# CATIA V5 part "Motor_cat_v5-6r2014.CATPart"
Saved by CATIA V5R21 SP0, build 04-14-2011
Part number: Motor
Bounding box of the stored display mesh (mm): x -152.4 to 152.4, y -76.2 to 165.1, z -171.45 to 152.4
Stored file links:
  D:\CATIA V5R21 E-RESOURCES\CATIA-V5R21\catia-v5r21-Tut\c12-catia-v5r21-tut\c12-catia-v5r21-tut01\Motor_cat_v5r21.CATPart
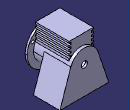
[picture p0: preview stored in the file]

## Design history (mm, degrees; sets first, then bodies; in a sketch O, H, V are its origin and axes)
Body1 (main body)
  Sketch1 on zx-plane, origin (0, 0, 0), H (-1, 0, 0), V (0, 0, 1)
    arc A1 centre (0, 0) radius 88.9 from (84.1413, 28.6959) to (-84.1413, 28.6959) ccw
    line L1 (-152.4, -171.45) -> (152.4, -171.45)
    point P1 (-152.4, -171.45)
    line L2 (152.4, -171.45) -> (84.1413, 28.6959)
    line L3 (-152.4, -171.45) -> (-84.1413, 28.6959)
    point P4 (-84.1413, 28.6959)
    point P5 (-84.1413, 28.6959)
    radius A1 = 88.9
    length L1 = 304.8
    distance V P1 = 152.4
    distance H L1 = 171.45
    horizontal: L1 H
    tangency: L3 A1, L2 A1
    coincidence: L3 P5, P4 A1, P4 P5
  Pad1: profile Sketch1, direction (0, 1, 0), length 165.1
  Sketch2 on face of Pad1, origin (0, 165.1, 0), H (-1, 0, 0), V (0, 0, 1)
    circle A1 centre (0, 0) radius 88.9
    reference projected arc E1 centre (0, 0) radius 88.9 from (84.1413, 28.6959) to (-84.1413, 28.6959) ccw from edge of Pad1
    tangency: A1 E1
  Pad2: profile Sketch2, direction (0, -1, 0), length 228.6
  Sketch3 on xy-plane, origin (0, 0, 0), H (1, 0, 0), V (0, 1, 0)
    line L1 (-76.2, 146.05) -> (76.2, 146.05)
    line L2 (76.2, 146.05) -> (76.2, -63.5)
    line L3 (76.2, -63.5) -> (-76.2, -63.5)
    line L4 (-76.2, -63.5) -> (-76.2, 146.05)
    reference projected line E1 (-88.9, -63.5) -> (88.9, -63.5) from edge of Pad2
    reference projected line E2 (84.1413, 165.1) -> (-84.1413, 165.1) from edge of Pad1
    length L1 = 152.4
    distance L4 V = 76.2
    distance E2 L1 = 19.05
    horizontal: L1 H, L3 H
    vertical: L2 V, L4 V
    coincidence: E1 L3
  Pad3: profile Sketch3, direction (0, 0, 1), length 152.4
  Sketch4 on face of Pad2, origin (0, -63.5, 0), H (1, 0, 0), V (0, 0, 1)
    circle A1 centre (0, 0) radius 127
    radius A1 = 127
  Pad4: profile Sketch4, direction (0, -1, 0), length 12.7
  Sketch5 on face of Pad3, origin (0, 146.05, 0), H (-1, 0, 0), V (0, 0, 1)
    line L1 (-76.2, 73.152) -> (-63.5, 73.152)
    line L2 (-63.5, 73.152) -> (-63.5, 61.722)
    line L3 (-63.5, 61.722) -> (-76.2, 61.722)
    line L4 (-76.2, 61.722) -> (-76.2, 73.152)
    reference projected line E1 (-76.2, 0) -> (-76.2, 152.4) from edge of Pad3
    length L1 = 12.7
    length L2 = 11.43
    distance L3 H = 61.722
    horizontal: L1 H, L3 H
    vertical: L2 V, L4 V
    coincidence: L4 E1
  Pocket1: profile Sketch5, direction (0, -1, 0), length 209.55
  RectPattern1: of Pocket1, direction 1 instances 4, spacing 22.86, along edge of Pad3 reversed, direction 2 instances 2, spacing 139.7, along edge of Pad3
  Sketch6 on face of Pad4, origin (0, -76.2, 0), H (1, 0, 0), V (0, 0, 1)
    circle A1 centre (0, -107.95) radius 9.525
    point P1 (0, -107.95)
    radius A1 = 9.525
    distance P1 H = 107.95
    coincidence: P1 V
  Pocket2: profile Sketch6, direction (0, 1, 0), length 12.7
  CircPattern1: of Pocket2, instances 3, angular step 120, axis from face
  Sketch7 on face of Pad4, origin (0, -76.2, 0), H (1, 0, 0), V (0, 0, 1)
    circle A1 centre (0, 0) radius 76.2
    circle A2 centre (0, 0) radius 19.05
    radius A1 = 76.2
    radius A2 = 19.05
  MultiPocket1: profile Sketch7, domains (length 254; length 228.6)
